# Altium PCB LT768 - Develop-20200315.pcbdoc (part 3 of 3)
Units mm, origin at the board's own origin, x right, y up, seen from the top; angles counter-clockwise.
Board outline 114.72 x 114.74 mm, 2 copper layers (Top Layer, Bottom Layer); 164 components, 138 nets, 704 pads, 858 vias.
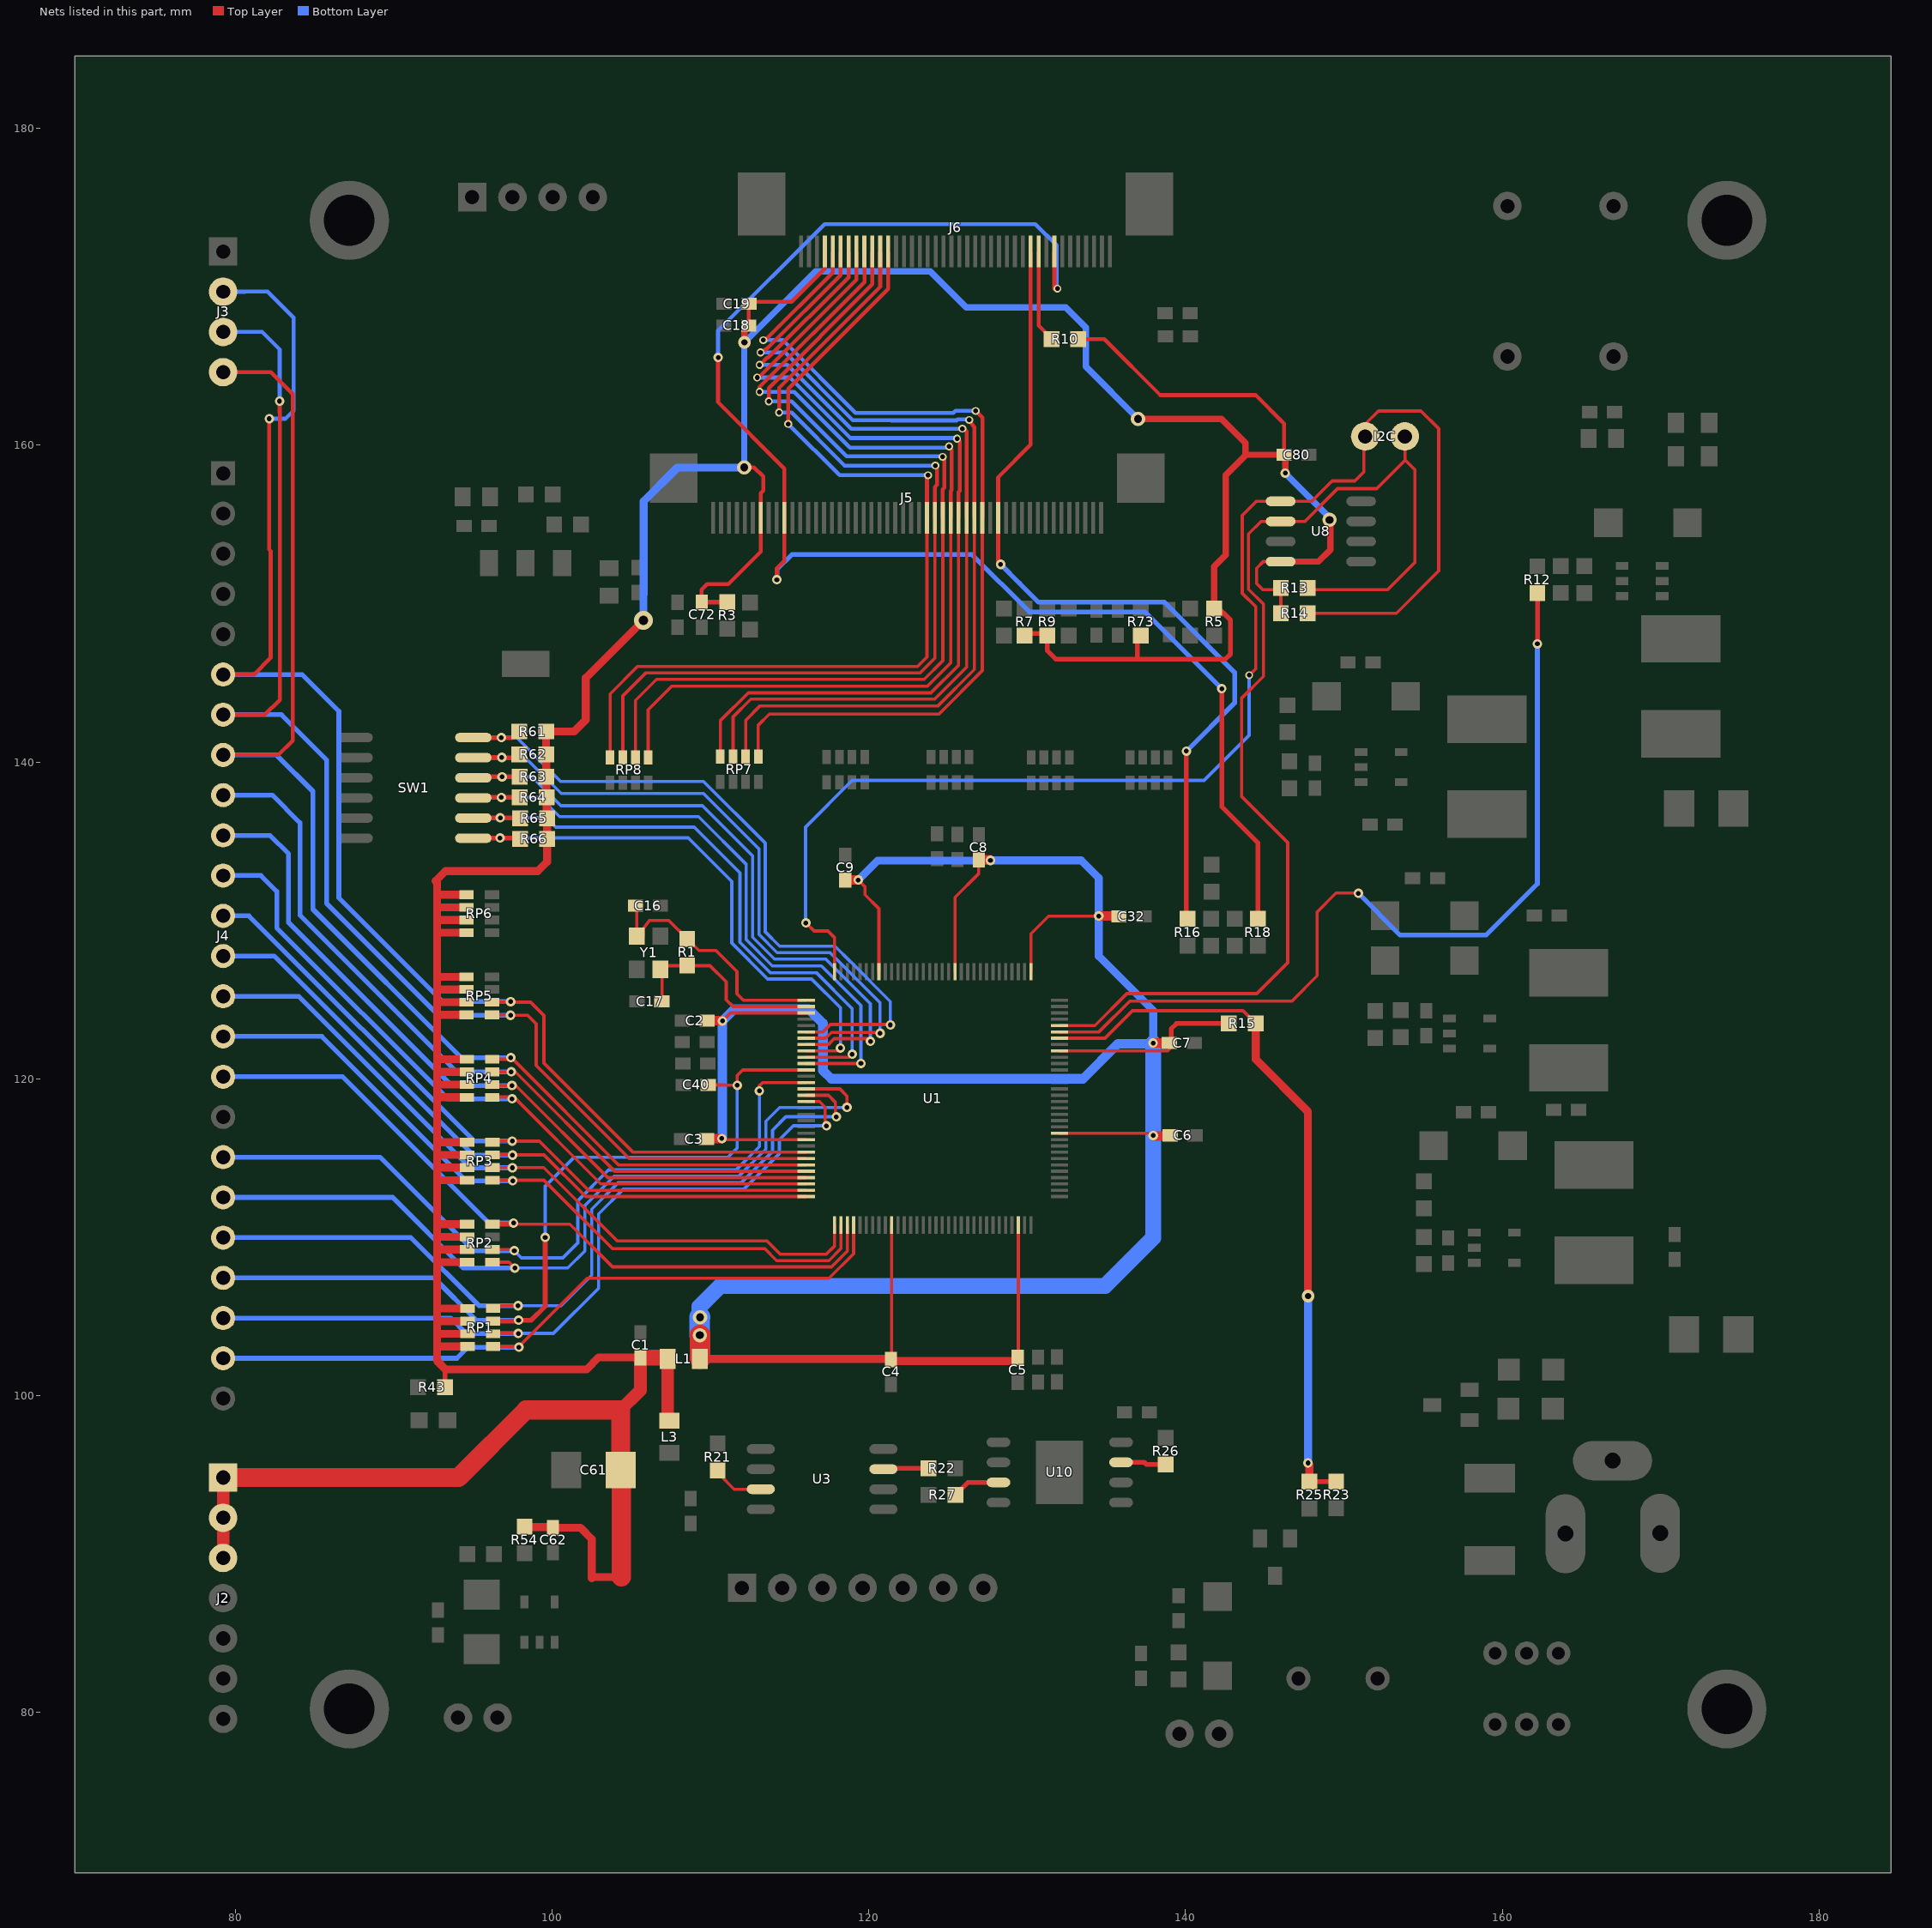
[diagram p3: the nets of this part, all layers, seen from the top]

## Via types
v1: diameter 0.6, hole 0.3, Top Layer to Bottom Layer, 743 vias
v2: diameter 0.5, hole 0.3, Top Layer to Bottom Layer, 82 vias
v3: diameter 0.9, hole 0.5, Top Layer to Bottom Layer, 20 vias
v4: diameter 1.2, hole 0.6, Top Layer to Bottom Layer, 7 vias
v5: diameter 0.8, hole 0.4, Top Layer to Bottom Layer, 6 vias

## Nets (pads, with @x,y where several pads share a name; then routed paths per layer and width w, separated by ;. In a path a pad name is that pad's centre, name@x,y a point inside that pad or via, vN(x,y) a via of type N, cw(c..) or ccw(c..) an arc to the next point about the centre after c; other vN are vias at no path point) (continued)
LT768_DB5_SDO: J3.2 J4.6 RP5.2 U1.25 | length 114.5
  Top Layer w0.2: RP5.2@96.55,124.84 v1@97.38,124.84 ; v1(97.38,124.87) v1@97.38,124.84 ; v1@97.38,124.84 98.64,124.84 ; v1@97.38,124.84 98.64,124.84 ; 98.64,124.84 99.48,124 ; 98.64,124.84 99.48,124 ; 99.48,120.994 105.114,115.36 ; 99.48,120.994 99.48,124 ; 99.48,120.994 105.114,115.36 ; 99.48,120.994 99.48,124 ; 105.114,115.36 U1.25@116.04,115.36 105.114,115.36
  Top Layer w0.25: J4.6@79.22,145.53 81.17,145.53 82.22,146.58 82.22,153.33 82.13,153.42 v1(82.13,161.68)
  Bottom Layer w0.25: J3.2@79.22,169.7 80.62,169.7 80.63,169.71 82.03,169.71 83.67,168.07 83.67,162.19 83.16,161.68 v1(82.13,161.68)
  Bottom Layer w0.3: J4.6@79.22,145.53 84.21,145.53 86.53,143.21 86.53,131.43 93.09,124.87 v1(97.38,124.87)
LT768_DB6_SDI: J3.3 J4.7 RP5.1 U1.26 | length 87.8
  Top Layer w0.2: U1.26@116.04,114.96 104.87,114.96 98.99,120.84 98.99,123.47 98.45,124.01 v1(97.37,124.01) ; v1(97.37,124.01) v1@97.37,124.04 ; v1(97.37,124.01) v1@97.37,124.04 ; v1@97.37,124.04 RP5.1@96.2,124.04 v1@97.37,124.04
  Top Layer w0.25: J4.7@79.22,142.99 81.86,142.99 82.795,143.925 82.795,162.045 82.79,162.05 v1(82.79,162.79)
  Bottom Layer w0.25: J3.3@79.22,167.16 81.68,167.16 82.79,166.05 v1(82.79,162.79)
  Bottom Layer w0.3: J4.7@79.22,142.99 82.9,142.99 85.75,140.14 85.75,131.08 92.82,124.01 v1(97.37,124.01)
  other v1: 97.37,124.01
LT768_DB7_SCLK: J3.4 J4.8 RP4.4 U1.27 | length 105.8
  Top Layer w0.2: RP4.4@96.56,121.23 v1@97.4,121.23 ; v1(97.39,121.34) 97.4,121.33 v1@97.4,121.23 ; v1@97.4,121.23 v1@97.526,121.23 ; v1@97.4,121.23 v1@97.526,121.23 ; v1@97.526,121.23 104.196,114.56 ; v1@97.526,121.23 104.196,114.56 ; 104.196,114.56 U1.27@116.04,114.56 104.196,114.56
  Top Layer w0.25: J4.8@79.22,140.45 82.71,140.45 83.61,141.35 83.61,163.24 82.23,164.62 J3.4@79.22,164.62
  Bottom Layer w0.3: J4.8@79.22,140.45 82.59,140.45 84.89,138.15 84.89,130.7 94.25,121.34 v1(97.39,121.34)
LT768_DB8: J4.9 RP4.3 U1.28 | length 72.2
  Top Layer w0.2: RP4.3@96.56,120.43 96.57,120.44 v1(97.41,120.44) ; v1(97.41,120.44) v1@97.426,120.456 ; v1(97.41,120.44) v1@97.426,120.456 ; v1@97.426,120.456 v1@97.65,120.456 ; v1@97.426,120.456 v1@97.65,120.456 ; v1@97.65,120.456 103.946,114.16 ; v1@97.65,120.456 103.946,114.16 ; 103.946,114.16 U1.28@116.04,114.16 103.946,114.16
  Bottom Layer w0.3: J4.9@79.22,137.91 82.33,137.91 84.07,136.17 84.07,130.33 93.96,120.44 v1(97.41,120.44)
  other v1: 97.41,120.44
LT768_DB9: J4.10 RP4.2 U1.29 | length 70.3
  Top Layer w0.2: RP4.2@96.56,119.63 96.56,119.57 v1(97.46,119.57) ; v1(97.46,119.57) v1@97.7,119.57 ; v1(97.46,119.57) v1@97.7,119.57 ; v1@97.7,119.57 103.51,113.76 ; v1@97.7,119.57 103.51,113.76 ; 103.51,113.76 U1.29@116.04,113.76 103.51,113.76
  Bottom Layer w0.3: J4.10@79.22,135.37 82.18,135.37 83.35,134.2 83.35,129.86 93.64,119.57 v1(97.46,119.57)
  other v1: 97.46,119.57
LT768_DB10: J4.11 RP4.1 U1.30 | length 68.2
  Top Layer w0.2: RP4.1@96.56,118.83 96.56,118.85 v1@97.47,118.85 ; v1(97.47,118.73) v1@97.47,118.85 ; v1@97.47,118.85 v1@97.58,118.85 ; v1@97.47,118.85 v1@97.58,118.85 ; v1@97.58,118.85 103.07,113.36 ; v1@97.58,118.85 103.07,113.36 ; 103.07,113.36 U1.30@116.04,113.36 103.07,113.36
  Bottom Layer w0.3: J4.11@79.22,132.83 81.61,132.83 82.61,131.83 82.61,129.53 93.41,118.73 v1(97.47,118.73)
LT768_DB11: J4.12 RP3.4 U1.31 | length 64.8
  Top Layer w0.2: RP3.4@96.58,115.995 96.645,116.06 v1(97.48,116.06) ; v1(97.48,116.06) 99.2,116.06 ; v1(97.48,116.06) 99.2,116.06 ; 99.2,116.06 102.3,112.96 ; 99.2,116.06 102.3,112.96 ; 102.3,112.96 U1.31@116.04,112.96 102.3,112.96
  Bottom Layer w0.3: J4.12@79.22,130.29 80.85,130.29 95.08,116.06 v1(97.48,116.06)
  other v1: 97.48,116.06
LT768_DB12: J4.13 RP3.3 U1.32 | length 67.9
  Top Layer w0.2: RP3.3@96.58,115.195 v1@97.47,115.195 ; U1.32@116.04,112.56 102.12,112.56 99.485,115.195 v1@97.489,115.195 ; v1@97.47,115.195 v1(97.5,115.18) ; v1@97.47,115.195 v1(97.5,115.18) ; v1@97.47,115.195 v1@97.485,115.195 ; v1@97.47,115.195 v1@97.47,115.24 ; v1@97.47,115.195 v1@97.47,115.24 ; v1@97.47,115.195 v1@97.485,115.195 ; v1@97.47,115.195 v1(97.5,115.18) ; v1@97.47,115.24 v1@97.489,115.195 ; v1@97.47,115.24 v1@97.489,115.195 ; v1@97.485,115.195 v1@97.489,115.195 ; v1@97.485,115.195 v1@97.489,115.195 ; v1@97.485,115.195 v1(97.5,115.18) ; v1@97.485,115.195 v1(97.5,115.18) ; v1@97.489,115.195 97.5,115.184 v1(97.5,115.18)
  Bottom Layer w0.3: 82.43,127.75 95,115.18 ; 82.43,127.75 J4.13@79.22,127.75 82.43,127.75 ; 82.43,127.75 95,115.18 ; 95,115.18 v1(97.5,115.18) 95,115.18
  other v1: 97.5,115.18
LT768_DB13: J4.14 RP3.2 U1.33 | length 72
  Top Layer w0.2: RP3.2@96.58,114.395 v1@97.505,114.395 ; v1(97.49,114.38) v1@97.505,114.395 ; v1@97.505,114.395 99.471,114.395 ; v1@97.505,114.395 99.471,114.395 ; 99.471,114.395 104.106,109.76 ; 99.471,114.395 104.106,109.76 ; 104.106,109.76 113.57,109.76 ; 104.106,109.76 113.57,109.76 ; 113.57,109.76 114.41,108.92 ; 113.57,109.76 114.41,108.92 ; 114.41,108.92 117.31,108.92 ; 114.41,108.92 117.31,108.92 ; 117.31,108.92 117.84,109.45 ; 117.31,108.92 117.84,109.45 ; 117.84,109.45 U1.33@117.84,110.76 117.84,109.45
  Bottom Layer w0.3: J4.14@79.22,125.21 83.99,125.21 94.82,114.38 v1(97.49,114.38)
LT768_DB14: J4.15 RP3.1 U1.34 | length 72.3
  Top Layer w0.2: RP3.1@96.58,113.595 v1@97.54,113.595 ; v1(97.51,113.56) 97.51,113.565 v1@97.54,113.595 ; v1@97.54,113.595 99.485,113.595 ; v1@97.54,113.595 99.485,113.595 ; 99.485,113.595 103.81,109.27 ; 99.485,113.595 103.81,109.27 ; 103.81,109.27 113.432,109.27 ; 103.81,109.27 113.432,109.27 ; 113.432,109.27 114.182,108.52 ; 113.432,109.27 114.182,108.52 ; 114.182,108.52 117.476,108.52 ; 114.182,108.52 117.476,108.52 ; 117.476,108.52 118.24,109.284 ; 117.476,108.52 118.24,109.284 ; 118.24,109.284 U1.34@118.24,110.76 118.24,109.284
  Bottom Layer w0.3: J4.15@79.22,122.67 85.45,122.67 94.56,113.56 v1(97.51,113.56)
LT768_DB15: J4.16 RP2.4 U1.35 | length 49.2
  Top Layer w0.2: v1@97.56,110.815 101.115,110.815 103.81,108.12 117.641,108.12 118.64,109.119 U1.35@118.64,110.76
  Top Layer w0.3: v1(97.56,110.89) v1@97.56,110.815 ; v1@97.56,110.815 RP2.4@96.231,110.815 v1@97.56,110.815
  Bottom Layer w0.3: J4.16@79.22,120.13 86.77,120.13 96.01,110.89 v1(97.56,110.89)
LT768_I2C_M_SCL: I2C.1 R13.2 U1.92 U8.6 | length 74.4
  Top Layer w0.2: U1.92@132.04,123.36 134.272,123.36 136.292,125.38 144.499,125.38 146.45,127.331 146.45,134.91 143.55,137.81 143.55,144.04 144.92,145.41 144.92,149.97 143.98,150.91 143.98,154.405 144.77,155.195 U8.6@146.01,155.195 147.535,155.195 149.6,157.26 152.07,157.26 153.86,159.05 ; R13.2@147.72,150.99 147.82,150.89 152.77,150.89 154.48,152.6 154.48,158.46 153.89,159.05 153.86,159.05 ; 153.86,159.05 I2C.1@153.86,160.55 ; 153.86,159.05 I2C.1@153.86,160.55 ; I2C.1@153.86,160.55 I2C.1@153.85,160.56 I2C.1@153.86,160.55
LT768_I2C_M_SDA: I2C.2 R14.2 U1.128 U8.5 | length 90.9
  Top Layer w0.2: v1(116.03,129.84) 116.54,129.33 117.41,129.33 117.84,128.9 U1.128@117.84,126.76 ; v2(144.02,145.48) 144.43,145.89 144.43,149.81 143.58,150.66 143.58,155.57 144.475,156.465 U8.5@146.01,156.465 147.975,156.465 149.26,157.75 150.69,157.75 151.26,158.32 151.26,160.47 I2C.2@151.35,160.56 151.35,161.34 152.18,162.17 154.87,162.17 155.99,161.05 155.99,152.07 153.32,149.4 R14.2@147.72,149.4
  Bottom Layer w0.2: v1(116.03,129.84) 116,129.84 116,135.89 118.95,138.84 141.17,138.84 144.02,141.69 v2(144.02,145.48)
LT768_INT: J4.23 RP1.1 U1.36 | length 47.7
  Top Layer w0.2: v1(97.9,103.05) v1@97.9,103.08 ; U1.36@119.04,110.76 119.04,108.953 117.487,107.4 102.22,107.4 v1@97.9,103.08 ; RP1.1@96.26,103.08 v1@97.9,103.08 ; RP1.1@96.26,103.08 RP1.1@96.26,103.096 RP1.1@96.26,103.08 ; RP1.1@96.26,103.08 v1@97.9,103.08
  Bottom Layer w0.3: J4.23@79.22,102.35 93.99,102.35 94.69,103.05 v1(97.9,103.05)
LT768_PS0: R64.1 SW1.9 U1.11 | length 42.2
  Top Layer w0.2: U1.11@116.04,120.96 v1@119.5,120.96 ; v1@119.48,120.96 v1@119.5,120.94 ; v1@119.48,120.96 v1(119.5,120.97) ; v1@119.48,120.96 v1(119.5,120.97) ; v1@119.48,120.96 v1@119.5,120.94 ; v1@119.5,120.94 v1@119.5,120.96 ; v1@119.5,120.94 v1@119.5,120.96 ; v1@119.5,120.96 v1(119.5,120.97)
  Top Layer w0.3: SW1.9@95.13,137.735 95.155,137.76 v1(96.79,137.76) ; v1(96.79,137.76) R64.1@97.95,137.76 v1(96.79,137.76)
  Bottom Layer w0.2: v1(96.79,137.76) 99.26,137.76 100.467,136.553 109.24,136.553 112.26,133.533 112.26,128.78 113.91,127.13 117,127.13 119.5,124.63 v1(119.5,120.97)
  other v1: 119.5,120.97 96.79,137.76
LT768_PS1: R65.1 SW1.8 U1.10 | length 40.4
  Top Layer w0.2: U1.10@116.04,121.36 118.76,121.36 v1(118.95,121.55) ; R65.1@98.025,136.48 R65.1@98.1,136.39 ; R65.1@98.025,136.48 98,136.48 R65.1@98.025,136.48 ; R65.1@98.025,136.48 R65.1@98.1,136.39 ; R65.1@98.04,136.45 R65.1@97.98,136.45 R65.1@98.04,136.45 ; R65.1@98.04,136.45 R65.1@98.1,136.39 ; R65.1@98.04,136.45 R65.1@98.1,136.39
  Top Layer w0.3: SW1.8@95.13,136.465 95.13,136.48 v1(96.72,136.48) ; v1(96.72,136.48) 98,136.48 v1(96.72,136.48)
  Bottom Layer w0.2: v1(96.72,136.48) 99.64,136.48 100.23,135.89 108.97,135.89 111.86,133 111.86,128.615 113.775,126.7 116.68,126.7 118.95,124.43 v1(118.95,121.55)
  other v1: 96.72,136.48
LT768_PS2: R66.1 SW1.7 U1.9 | length 37.2
  Top Layer w0.2: v1(96.71,135.21) 97.98,135.21 R66.1@97.98,135.14 ; U1.9@116.04,121.76 118.03,121.76 v1(118.21,121.94)
  Top Layer w0.3: SW1.7@95.13,135.195 97.925,135.195 R66.1@97.98,135.14
  Bottom Layer w0.2: v1(96.71,135.21) 108.59,135.21 111.34,132.46 111.34,128.569 113.609,126.3 116.39,126.3 118.21,124.48 v1(118.21,121.94)
LT768_PWM0: R15.2 R23.1 R25.1 U1.90 | length 45.8
  Top Layer w0.2: U1.90@132.04,122.56 134.92,122.56 136.65,124.29 143.63,124.29 R15.2@144.43,123.49 ; v5@147.73,106.28 v5(147.74,106.28) ; R23.1@149.516,94.574 149.658,94.574 R23.1@149.67,94.563
  Top Layer w0.3: v1(147.73,95.74) v1@147.828,95.642 ; R25.1@147.828,94.563 R23.1@149.67,94.563
  Top Layer w0.5: R15.2@144.43,123.49 144.43,121.23 147.73,117.93 v5@147.73,106.28 ; R25.1@147.828,94.563 v1@147.828,95.642
  Bottom Layer w0.5: v1(147.73,95.74) 147.74,95.74 v5(147.74,106.28)
LT768_PWM1: R12.1 U1.91 | length 57
  Top Layer w0.2: U1.91@132.04,122.96 134.53,122.96 136.48,124.91 146.72,124.91 148.31,126.5 148.31,130.53 149.505,131.725 150.905,131.725 v1(150.92,131.71) ; R12.1@162.22,150.66 R12.1@162.24,150.63
  Top Layer w0.3: v1(162.22,147.46) 162.24,147.48 R12.1@162.24,150.63
  Bottom Layer w0.3: v1(150.92,131.71) 153.56,129.07 158.98,129.07 162.22,132.31 v1(162.22,147.46)
LT768_RD#: J4.18 RP2.2 U1.14 | length 69.8
  Top Layer w0.2: RP2.2@96.581,109.215 97.535,109.215 v1(97.61,109.14) ; v1(113.09,119.23) 113.09,119.54 113.08,119.55 113.29,119.76 U1.14@116.04,119.76
  Bottom Layer w0.2: v1(97.61,109.14) 98.06,108.69 100.669,108.69 101.62,109.641 101.62,112.3 103.56,114.24 111.61,114.24 113.09,115.72 v1(113.09,119.23)
  Bottom Layer w0.3: 89.12,115.05 J4.18@79.22,115.05 89.12,115.05 ; 89.12,115.05 95.03,109.14 ; 89.12,115.05 95.03,109.14 ; 95.03,109.14 v1(97.61,109.14) 95.03,109.14
  other v1: 97.61,109.14
LT768_RS/A0: J4.20 RP1.4 U1.16 | length 73.4
  Top Layer w0.2: RP1.4@96.61,105.496 96.784,105.67 v1(97.85,105.67) ; U1.16@116.04,118.96 117.45,118.96 117.88,118.53 117.88,117.69 117.95,117.62 v1(117.95,117.6)
  Bottom Layer w0.2: v1(97.85,105.67) 100.58,105.67 102.5,107.59 102.5,111.77 104.16,113.43 111.936,113.43 113.92,115.414 113.92,116.756 114.764,117.6 v1(117.95,117.6)
  Bottom Layer w0.3: 91.08,109.97 J4.20@79.22,109.97 91.08,109.97 ; 91.08,109.97 95.38,105.67 ; 91.08,109.97 95.38,105.67 ; 95.38,105.67 v1(97.85,105.67) 95.38,105.67
  other v1: 97.85,105.67
LT768_RST: C40.1 J4.21 RP1.3 U1.12 | length 58.6
  Top Layer w0.2: U1.12@116.04,120.56 112.04,120.56 111.69,120.21 v1(111.69,119.59) ; 110.889,119.611 C40.1@109.861,119.611 110.889,119.611 ; 110.889,119.611 110.91,119.59 ; 110.889,119.611 110.91,119.59 ; 110.91,119.59 v1(111.69,119.59) ; 110.91,119.59 v1(111.69,119.59)
  Top Layer w0.3: v1(99.56,109.98) 99.56,105.64 98.68,104.76 v1(97.88,104.76) ; v1@97.88,104.696 v1(97.88,104.76) ; v1@97.88,104.696 RP1.3@96.26,104.696 v1@97.88,104.696 ; v1@97.88,104.696 v1(97.88,104.76)
  Bottom Layer w0.2: v1(99.56,109.98) 99.56,113.21 101.4,115.05 111.11,115.05 111.69,115.63 v1(111.69,119.59)
  Bottom Layer w0.3: J4.21@79.22,107.43 92.53,107.43 95.2,104.76 v1(97.88,104.76)
  other v1: 97.88,104.76 111.69,119.59
LT768_TEST[0]: R63.1 SW1.10 U1.8 | length 43.5
  Top Layer w0.2: SW1.10@95.185,139.06 95.195,139.07 SW1.10@95.53,139.07 ; U1.8@116.04,122.16 117.44,122.16 117.81,122.53 119.99,122.53 120.11,122.41 v1(120.1,122.36)
  Top Layer w0.3: SW1.10@95.53,139.07 R63.1@97.94,139.07 ; v1(96.84,139.06) SW1.10@95.185,139.06 ; SW1.10@95.185,139.06 95.13,139.005 SW1.10@95.185,139.06
  Bottom Layer w0.2: v1(96.84,139.06) 98.73,139.06 100.55,137.24 109.49,137.24 112.66,134.07 112.66,128.946 114.046,127.56 114.737,127.56 114.74,127.563 117.28,127.563 120.1,124.743 v1(120.1,122.36)
LT768_TEST[1]: R62.1 SW1.11 U1.7 | length 44.8
  Top Layer w0.2: U1.7@116.04,122.56 117.27,122.56 117.64,122.93 120.438,122.93 v1(120.71,122.87)
  Top Layer w0.3: v1(96.82,140.29) 95.145,140.29 95.13,140.275 97.735,140.275 R62.1@97.93,140.47
  Bottom Layer w0.2: v1(96.82,140.29) 98.29,140.29 100.57,138.01 109.56,138.01 113.06,134.51 113.06,129.114 114.204,127.97 117.55,127.97 120.71,124.81 v1(120.71,122.87)
LT768_TEST[2]: R61.1 SW1.12 U1.6 | length 47.8
  Top Layer w0.2: U1.6@116.04,122.96 117.1,122.96 117.57,123.43 121.36,123.43 v1(121.36,123.4)
  Top Layer w0.3: SW1.12@95.13,141.545 R61.1@97.49,141.545 ; v1(96.79,141.54) 95.98,141.545 R61.1@97.49,141.545 ; R61.1@97.49,141.545 R61.1@97.775,141.83 ; R61.1@97.49,141.545 R61.1@97.775,141.83 ; R61.1@97.775,141.83 R61.1@97.92,141.83 ; R61.1@97.775,141.83 R61.1@97.92,141.83 ; R61.1@97.92,141.83 R61.1@97.92,141.93 R61.1@97.92,141.83
  Bottom Layer w0.2: v1(96.79,141.54) 97.77,141.54 100.53,138.78 109.56,138.78 113.46,134.88 113.46,129.28 114.37,128.37 117.856,128.37 118.822,127.404 118.833,127.404 121.36,124.877 v1(121.36,123.4)
LT768_VDD3.3V: C2.1 C3.1 C4.1 C5.1 C6.1 C7.1 C8.1 C9.1 C32.1 L1.2 R15.1 U1.3 U1.23 U1.42 U1.62 U1.75 U1.88 U1.97 U1.109 U1.121 | length 270.4
  Top Layer w0.2: C3.1@109.747,116.19 C3.1@109.787,116.23 ; v1@110.605,123.666 110.61,123.662 v1(110.75,123.65) ; C4.1@121.4,102.277 121.4,102.53 121.44,102.57 U1.42@121.44,110.76 ; U1.109@125.44,126.76 125.44,131.46 126.944,132.964 C8.1@126.944,133.825 ; C5.1@129.258,102.18 C5.1@129.4,102.397 129.44,102.397 U1.62@129.44,110.76 ; U1.88@132.04,121.76 138.87,121.76 139.01,121.9 139.01,122.23 C7.1@138.984,122.256 ; C32.1@135.769,130.27 C32.1@135.796,130.243 ; v1@137.97,116.39 137.97,116.41 v1(137.96,116.42) ; v1@110.75,116.23 v1@110.82,116.16 ; v1@110.75,116.23 v1(110.72,116.23) v1@110.75,116.23 ; v1@110.75,116.23 v1@110.82,116.16 ; v1(110.75,123.65) 111.26,124.16 ; v1(110.75,123.65) 111.26,124.16 ; v1(110.75,123.65) 111.26,124.16 ; v1@110.82,116.16 U1.23@116.04,116.16 v1@110.82,116.16 ; 111.26,124.16 U1.3@116.04,124.16 ; 111.26,124.16 U1.3@116.04,124.16 ; 111.26,124.16 U1.3@116.04,124.16 ; 119.754,131.626 119.754,132.126 ; 119.754,131.626 120.64,130.74 ; 119.754,131.626 119.754,132.126 ; 119.754,131.626 120.64,130.74 ; 119.754,132.126 v1(119.33,132.55) 119.754,132.126 ; 120.64,130.74 U1.121@120.64,126.76 120.64,130.74 ; U1.97@130.24,126.76 130.24,129.16 ; U1.97@130.24,126.76 130.24,129.16 ; U1.97@130.24,126.76 130.24,129.16 ; 130.24,129.16 131.35,130.27 ; 130.24,129.16 131.35,130.27 ; 130.24,129.16 131.35,130.27 ; 131.35,130.27 v1(134.52,130.27) ; 131.35,130.27 v1(134.52,130.27) ; 131.35,130.27 v1(134.52,130.27) ; U1.75@132.04,116.56 v1@137.82,116.56 ; U1.75@132.04,116.56 v1@137.82,116.56 ; U1.75@132.04,116.56 v1@137.82,116.56 ; U1.75@132.04,116.56 v1@137.82,116.56 ; v1@137.82,116.56 v1(137.96,116.42) ; v1@137.82,116.56 v1(137.96,116.42) ; v1@137.82,116.56 v1(137.96,116.42) ; v1@137.82,116.56 v1(137.96,116.42) ; C7.1@138.984,122.256 138.98,122.26 C7.1@138.984,122.256 ; v3@109.33,104.93 v3(109.34,104.94) v3@109.33,104.93 ; v1@127.645,133.825 v1(127.68,133.79) v1@127.645,133.825
  Top Layer w0.3: C7.1@138.984,122.256 138.984,122.314 139.09,122.42 139.09,123.15 139.43,123.49 R15.1@142.73,123.49
  Top Layer w0.5: L1.2@109.327,102.312 121.4,102.312 C4.1@121.4,102.277 121.52,102.18 C5.1@129.258,102.18 ; C9.1@118.509,132.543 C9.1@118.516,132.55
  Top Layer w0.6: C3.1@109.787,116.23 v1(110.72,116.23) ; C2.1@109.787,123.666 v1@110.605,123.666 ; C9.1@118.516,132.55 v1(119.33,132.55) ; v1(134.52,130.27) C32.1@135.769,130.27 ; v1@137.97,116.39 139.032,116.39 C6.1@139.032,116.426 ; C8.1@126.944,133.825 127.645,133.825 C8.1@126.944,133.825 ; v1(137.95,122.26) 138.98,122.26 v1(137.95,122.26)
  Top Layer w1: L1.2@109.327,102.312 L1.2@109.33,102.315
  Top Layer w1.3: L1.2@109.33,102.315 v3(109.33,103.81)
  Bottom Layer w0.2: v1(110.72,116.23) v1@110.75,116.26
  Bottom Layer w0.5: v1(119.33,132.55) 120.55,133.77 127.66,133.77 v1(127.68,133.79) 133.41,133.79 134.52,132.68 v1(134.52,130.27) 134.52,127.74 137.96,124.3 137.96,122.25 v1(137.95,122.26)
  Bottom Layer w0.6: v1@110.75,116.26 v1(110.75,123.65) 111.5,124.4 116.2,124.4 117.1,123.5 117.1,120.52 117.62,120 133.52,120 135.73,122.21 137.9,122.21 v1(137.95,122.26)
  Bottom Layer w1: v3@109.31,104.94 109.31,105.62 110.61,106.92 134.92,106.92 137.96,109.96 v1(137.96,116.42) ; v1(137.96,116.42) 137.96,122.25 v1(137.96,116.42)
  Bottom Layer w1.3: v3(109.33,103.81) 109.3,103.81 109.3,104.94 v3@109.31,104.94 ; v3@109.31,104.94 v3(109.34,104.94) v3@109.31,104.94
  other v1: 110.72,116.23 137.96,116.42 137.96,116.42 137.95,122.26 110.75,123.65 110.75,123.65 134.52,130.27 134.52,130.27 119.33,132.55 127.68,133.79
  other v3: 109.34,104.94
LT768_WAIT: J4.22 RP1.2 U1.17 | length 70.1
  Top Layer w0.2: RP1.2@96.61,103.896 96.634,103.92 v1(97.86,103.92) ; U1.17@116.04,118.56 116.89,118.56 117.24,118.21 117.24,117.17 117.33,117.08 v1(117.33,117.03)
  Bottom Layer w0.2: v1(97.86,103.92) 100.08,103.92 102.93,106.77 102.93,111.47 104.49,113.03 112.101,113.03 114.35,115.279 114.35,116.15 115.23,117.03 v1(117.33,117.03)
  Bottom Layer w0.3: 93.6,104.89 J4.22@79.22,104.89 93.6,104.89 ; 93.6,104.89 94.58,103.91 ; 93.6,104.89 94.58,103.91 ; 94.58,103.91 96.14,103.91 ; 94.58,103.91 96.14,103.91 ; 96.14,103.91 96.15,103.92 ; 96.14,103.91 96.15,103.92 ; 96.15,103.92 v1(97.86,103.92) 96.15,103.92
  other v1: 97.86,103.92
LT768_WR#: J4.19 RP2.1 U1.15 | length 73.1
  Top Layer w0.2: RP2.1@96.581,108.415 97.275,108.415 v1(97.64,108.05) ; U1.15@116.04,119.36 118.17,119.36 118.62,118.91 v1(118.62,118.19)
  Bottom Layer w0.2: v1(97.64,108.05) 100.98,108.05 102.06,109.13 102.06,111.99 103.91,113.84 111.78,113.84 113.5,115.56 113.5,117.32 114.37,118.19 v1(118.62,118.19)
  Bottom Layer w0.3: 89.93,112.51 J4.19@79.22,112.51 89.93,112.51 ; 89.93,112.51 94.39,108.05 ; 89.93,112.51 94.39,108.05 ; 94.39,108.05 v1(97.64,108.05) 94.39,108.05
  other v1: 97.64,108.05
LT768_XI: C16.1 R1.2 U1.1 Y1.3 | length 16.3
  Top Layer w0.2: C16.1@105.263,130.93 105.34,130.853 Y1.3@105.34,129.01 105.74,129.01 105.74,129.46 106.14,129.99 107.377,129.99 R1.2@108.527,128.84 109.267,128.1 110.34,128.1 111.67,126.77 111.67,125.37 112.08,124.96 U1.1@116.04,124.96
LT768_XO: C17.2 R1.1 U1.2 Y1.1 | length 13.3
  Top Layer w0.2: C17.2@106.937,124.89 106.937,126.91 Y1.1@106.84,126.91 106.84,127.14 R1.1@108.527,127.14 109.97,127.14 110.99,126.12 110.99,124.99 111.42,124.56 U1.2@116.04,124.56
M_FLASH_HOLD: R26.2 U10.7 | length 2.9
  Top Layer w0.3: U10.7@135.93,95.78 137.392,95.78 137.536,95.636 R26.2@138.748,95.636
M_FLASH_HOLD#: R21.2 U3.7 | length 3.3
  Top Layer w0.2: R21.2@110.45,95.27 110.58,95.14 110.58,95 111.5,94.08 U3.7@113.18,94.08
M_FLASH_WP: R27.1 U10.3 | length 3
  Top Layer w0.3: R27.1@125.471,93.711 126.27,94.51 U10.3@128.19,94.51
M_FLASH_WP#: R22.1 U3.3 | length 2.9
  Top Layer w0.2: U3.3@120.92,95.35 U3.3@120.97,95.4
  Top Layer w0.3: U3.3@120.97,95.4 R22.1@123.76,95.4
ON/OFF: J6.31 R10.1 | length 5.9
  Top Layer w0.25: J6.31@130.72,172.24 130.72,167.56 131.53,166.75 R10.1@131.53,166.71
PCLK: J5.37 J6.30 R16.1 | length 55.1
  Top Layer w0.25: v1(128.32,152.48) 128.17,152.63 J5.37@128.17,155.43 128.17,157.99 130.22,160.04 J6.30@130.22,172.24
  Top Layer w0.3: v1(140.05,140.69) 140.05,130.24 R16.1@140.13,130.1
  Bottom Layer w0.3: v1(128.32,152.48) 129.525,151.285 130.72,150.09 138.67,150.09 143.11,145.65 143.11,143.74 140.06,140.69 v1(140.05,140.69)
R0: J5.35 J6.5 RP7.5 | length 57.1
  Top Layer w0.2: RP7.5@113.019,140.346 113.019,142.339 113.71,143.03 124.426,143.03 127.17,145.774 J5.35@127.17,155.43
  Top Layer w0.25: v2(113.33,166.64) 113.39,166.58 117.72,170.911 J6.5@117.72,172.24 ; v2(126.75,162.17) 127.17,161.75 J5.35@127.17,155.43
  Bottom Layer w0.25: v2(113.33,166.64) 114.57,166.64 119.17,162.04 125.336,162.04 125.476,162.18 126.75,162.18 v2(126.75,162.17)
R1: J5.34 J6.6 RP7.6 | length 57.5
  Top Layer w0.2: RP7.6@112.219,140.346 112.219,142.64 113.129,143.55 124.38,143.55 126.67,145.84 J5.34@126.67,155.43
  Top Layer w0.25: v2(113.16,165.86) 113.17,165.846 113.649,166.18 118.22,170.751 J6.6@118.22,172.24 ; v2(126.34,161.6) 126.67,161.117 J5.34@126.67,155.43
  Bottom Layer w0.25: v2(113.16,165.86) 114.714,165.86 118.984,161.59 121.389,161.59 121.409,161.57 125.555,161.57 125.615,161.63 126.31,161.63 v2(126.34,161.6)
R2: J5.33 J6.7 RP7.7 | length 57.9
  Top Layer w0.2: RP7.7@111.419,140.346 111.419,140.579 111.43,140.59 111.43,142.85 112.55,143.97 124.16,143.97 126.17,145.98 J5.33@126.17,155.43
  Top Layer w0.25: v2(113.1,165.08) 113.113,165.067 113.577,165.53 113.635,165.53 118.72,170.615 J6.7@118.72,172.24 ; v2(125.9,161.05) 125.96,161.11 126.185,160.885 126.185,157 126.17,156.985 J5.33@126.17,155.43
  Bottom Layer w0.25: v2(113.1,165.08) 114.857,165.08 118.887,161.05 v2(125.9,161.05)
R3: J5.32 J6.8 RP7.8 | length 58.1
  Top Layer w0.2: RP7.8@110.619,140.346 110.619,142.605 112.384,144.37 123.92,144.37 125.67,146.12 J5.32@125.67,155.43
  Top Layer w0.25: v2(112.95,164.28) 112.997,164.233 119.22,170.457 J6.8@119.22,172.24 ; v2(125.57,160.42) 125.735,160.255 125.735,157.11 125.67,157.045 J5.32@125.67,155.43
  Bottom Layer w0.25: v2(112.95,164.28) 115.021,164.28 118.841,160.46 125.57,160.46 v2(125.57,160.42)
R4: J5.31 J6.9 RP8.5 | length 62.2
  Top Layer w0.2: RP8.5@106.06,140.3 106.06,143.3 107.54,144.78 123.69,144.78 125.17,146.26 J5.31@125.17,155.43
  Top Layer w0.25: v2(113.1,163.37) 113.1,163.683 119.72,170.303 J6.9@119.72,172.24 ; v2(125.07,159.93) 125.235,159.744 125.235,157.17 125.17,157.105 J5.31@125.17,155.43
  Bottom Layer w0.25: v2(113.1,163.37) 115.294,163.37 118.814,159.85 125.043,159.85 125.043,159.903 v2(125.07,159.93)
R5: J5.30 J6.10 RP8.6 | length 61.6
  Top Layer w0.2: RP8.6@105.26,140.3 105.26,143.89 106.59,145.22 123.49,145.22 124.67,146.4 J5.30@124.67,155.43
  Top Layer w0.25: v2(113.68,162.78) 113.68,163.623 120.22,170.163 J6.10@120.22,172.24 ; v2(124.66,159.27) 124.775,159.155 124.775,157.33 124.67,157.225 J5.30@124.67,155.43
  Bottom Layer w0.25: v2(113.68,162.78) 115.12,162.78 118.6,159.3 124.66,159.3 v2(124.66,159.27)
R6: J5.29 J6.11 RP8.7 | length 60.9
  Top Layer w0.2: RP8.7@104.46,140.3 104.46,144.18 105.9,145.62 123.23,145.62 124.17,146.56 J5.29@124.17,155.43
  Top Layer w0.25: v2(114.33,162.07) 114.33,163.628 120.72,170.018 J6.11@120.72,172.24 ; J5.29@124.17,155.43 124.17,157.365 124.315,157.51 124.315,158.605 v2(124.2,158.72)
  Bottom Layer w0.25: v2(114.33,162.07) 115.12,162.07 118.47,158.72 v2(124.2,158.72)
R7: J5.28 J6.12 RP8.8 | length 60.2
  Top Layer w0.2: RP8.8@103.66,140.3 103.66,144.3 105.39,146.03 123.07,146.03 123.67,146.63 J5.28@123.67,155.43
  Top Layer w0.25: v2(114.91,161.35) 114.91,163.567 121.22,169.877 J6.12@121.22,172.24 ; J5.28@123.67,155.43 123.67,158.04 v2(123.74,158.11)
  Bottom Layer w0.25: v2(114.91,161.35) 118.15,158.11 v2(123.74,158.11)
VDD_3.3V: C1.1 C18.1 C19.1 C61.1 C62.1 C72.1 C80.1 J2.1 J2.2 J2.3 J5.7 J6.4 L1.1 L3.1 R3.1 R5.1 R7.1 R9.1 R10.2 R13.1 R14.1 R43.1 R54.2 R61.2 R62.2 R63.2 R64.2 R65.2 R66.2 R73.2 RP1.5 RP1.6 RP1.7 RP1.8 RP2.5 RP2.6 RP2.7 RP2.8 RP3.5 RP3.6 RP3.7 RP3.8 RP4.5 RP4.6 RP4.7 RP4.8 RP5.5 RP5.6 RP5.7 RP5.8 RP6.5 RP6.6 RP6.7 RP6.8 U8.8 | length 490.5
  Top Layer w0.2: L3.1@107.295,98.68 107.41,98.565 L3.1@107.41,98.406 ; U8.8@146.01,152.655 144.91,152.655 144.49,152.235 144.49,151.28 ; R14.1@146.02,149.4 R13.1@146.02,150.89 ; 144.49,151.28 144.88,150.89 ; 144.49,151.28 144.88,150.89 ; 144.49,151.28 144.88,150.89 ; 144.88,150.89 R13.1@146.02,150.89 ; 144.88,150.89 R13.1@146.02,150.89 ; 144.88,150.89 R13.1@146.02,150.89 ; R13.1@146.02,150.89 R13.1@146.02,150.99 R13.1@146.02,150.89
  Top Layer w0.25: C72.1@109.45,150.092 109.44,150.102 109.44,150.83 109.44,150.89 109.79,151.24 111.13,151.24 113.17,153.28 J5.7@113.17,155.43 ; J6.4@117.22,172.24 117.22,171.153 115.127,169.06 C19.1@112.417,169.06 ; R10.2@133.23,166.71 134.87,166.71 138.41,163.17 144.43,163.17 146.225,161.375 C80.1@146.225,159.402 C80.1@146.225,159.57 ; C18.1@112.24,167.56 C18.1@112.417,167.56 ; C18.1@112.24,167.56 112.14,167.46 C18.1@112.24,167.56 ; C18.1@112.24,167.56 C18.1@112.417,167.56 ; C19.1@112.32,169.06 C19.1@112.437,168.943 ; C19.1@112.32,169.06 C19.1@112.417,169.06 ; C19.1@112.32,169.06 C19.1@112.437,168.943 ; C19.1@112.32,169.06 C19.1@112.417,169.06 ; C18.1@112.417,167.56 C19.1@112.417,169.06 ; C19.1@112.437,168.943 C19.1@112.437,168.93 C19.1@112.437,168.943 ; 112.75,158.61 113.33,158.03 ; 112.75,158.61 v3(112.13,158.61) 112.75,158.61 ; 112.75,158.61 113.33,158.03 ; J5.7@113.17,155.43 113.17,156.98 ; J5.7@113.17,155.43 113.17,156.98 ; 113.17,156.98 113.33,157.14 ; 113.17,156.98 113.33,157.14 ; 113.33,157.14 113.33,158.03 ; 113.33,157.14 113.33,158.03
  Top Layer w0.3: C72.1@109.468,150.11 R3.1@111.07,150.11 ; R7.1@129.84,147.99 129.84,148.118 131.277,148.118 131.277,147.03 131.807,146.5 136.95,146.5 ; R5.1@141.81,149.69 141.81,149.92 141.88,149.92 142.84,148.96 142.84,146.82 142.52,146.5 136.95,146.5 ; 93.237,101.597 R43.1@93.237,100.526 93.237,101.597 ; 93.237,101.597 93.28,101.64 93.237,101.597 ; 136.95,146.5 R73.2@136.95,148.071 ; 136.95,146.5 R73.2@136.95,148.071 ; R73.2@136.95,148.071 R73.2@137.066,148.187 ; R73.2@136.95,148.071 R73.2@137.066,148.187 ; R73.2@137.066,148.187 R73.2@137.17,147.99 R73.2@137.066,148.187
  Top Layer w0.4: R5.1@141.81,149.69 141.81,152.355 142.54,153.085 142.54,158.12 143.792,159.372 ; U8.8@146.01,152.655 148.39,152.655 149.14,153.405 149.14,155.24 v3(149.09,155.29) ; C80.1@146.225,159.402 143.762,159.402 143.792,159.372 ; C80.1@146.225,159.57 146.3,159.495 v1(146.3,158.24) ; 142.265,161.67 143.792,160.143 ; 142.265,161.67 v3(137,161.67) 142.265,161.67 ; 142.265,161.67 143.792,160.143 ; 143.792,159.372 143.792,160.143 ; 143.792,159.372 143.792,160.143 ; v5(112.14,166.5) 112.14,167.46 v5(112.14,166.5)
  Top Layer w0.5: R54.2@98.26,91.73 98.26,91.686 100.06,91.686 C62.1@100.06,91.657 101.78,91.657 102.5,90.937 102.5,88.47 102.56,88.53 104.37,88.53 ; C61.1@104.324,95.29 C61.1@104.37,95.245 ; 105.554,100.32 105.58,100.32 ; C1.1@105.58,102.383 105.553,102.41 102.94,102.41 102.17,101.64 93.28,101.64 92.73,102.19 92.73,103.096 ; L1.1@107.224,102.383 L1.1@107.295,102.312 ; C72.1@109.45,150.092 C72.1@109.468,150.11 ; 92.635,132.485 93.26,133.11 ; 92.635,132.485 92.73,132.39 ; 92.635,132.485 92.73,132.39 ; 92.635,132.485 93.26,133.11 ; 92.73,103.096 RP1.8@94.66,103.096 92.73,103.096 ; 92.73,103.096 92.73,103.896 ; 92.73,103.896 RP1.7@94.66,103.896 92.73,103.896 ; 92.73,103.896 92.73,104.696 ; 92.73,104.696 92.73,105.496 ; 92.73,104.696 RP1.6@94.66,104.696 92.73,104.696 ; 92.73,105.496 RP1.5@94.66,105.496 92.73,105.496 ; 92.73,105.496 92.73,108.415 ; 92.73,108.415 RP2.8@94.631,108.415 92.73,108.415 ; 92.73,108.415 92.73,109.215 ; 92.73,109.215 RP2.7@94.631,109.215 92.73,109.215 ; 92.73,109.215 92.73,110.015 ; 92.73,110.015 RP2.6@94.631,110.015 92.73,110.015 ; 92.73,110.015 92.73,110.815 ; 92.73,110.815 RP2.5@94.631,110.815 92.73,110.815 ; 92.73,110.815 92.73,113.595 ; 92.73,113.595 94.28,113.595 92.73,113.595 ; 92.73,113.595 92.73,114.395 ; 92.73,114.395 94.28,114.395 92.73,114.395 ; 92.73,114.395 92.73,115.195 ; 92.73,115.195 94.28,115.195 92.73,115.195 ; 92.73,115.195 92.73,115.995 ; 92.73,115.995 RP3.5@94.28,115.995 ; 92.73,115.995 RP3.5@94.28,115.995 ; 92.73,115.995 92.73,118.83 ; 92.73,115.995 92.73,118.83 ; 92.73,115.995 RP3.5@94.28,115.995 ; 92.73,118.83 RP4.8@94.61,118.83 92.73,118.83 ; 92.73,118.83 92.73,119.63 ; 92.73,118.83 92.73,119.63 ; 92.73,119.63 92.73,120.43 ; 92.73,119.63 RP4.7@94.61,119.63 92.73,119.63 ; 92.73,119.63 92.73,120.43 ; 92.73,120.43 92.73,121.23 ; 92.73,120.43 RP4.6@94.61,120.43 92.73,120.43 ; 92.73,120.43 92.73,121.23 ; 92.73,121.23 92.73,124.04 ; 92.73,121.23 RP4.5@94.61,121.23 92.73,121.23 ; 92.73,121.23 92.73,124.04 ; 92.73,124.04 92.73,124.84 ; 92.73,124.04 RP5.8@94.6,124.04 92.73,124.04 ; 92.73,124.04 92.73,124.84 ; 92.73,124.84 92.73,125.64 ; 92.73,124.84 RP5.7@94.6,124.84 92.73,124.84 ; 92.73,124.84 92.73,125.64 ; 92.73,125.64 92.73,126.44 ; 92.73,125.64 RP5.6@94.6,125.64 92.73,125.64 ; 92.73,125.64 92.73,126.44 ; 92.73,126.44 92.73,129.22 ; 92.73,126.44 RP5.5@94.6,126.44 92.73,126.44 ; 92.73,126.44 92.73,129.22 ; 92.73,129.22 92.73,130.02 ; 92.73,129.22 RP6.8@94.6,129.22 92.73,129.22 ; 92.73,129.22 92.73,130.02 ; 92.73,130.02 92.73,130.82 ; 92.73,130.02 RP6.7@94.6,130.02 92.73,130.02 ; 92.73,130.02 92.73,130.82 ; 92.73,130.82 92.73,131.62 ; 92.73,130.82 RP6.6@94.6,130.82 92.73,130.82 ; 92.73,130.82 92.73,131.62 ; 92.73,131.62 92.73,132.39 ; 92.73,131.62 RP6.5@94.6,131.62 92.73,131.62 ; 92.73,131.62 92.73,132.39 ; 93.26,133.11 99.09,133.11 ; 93.26,133.11 99.09,133.11 ; 99.09,133.11 99.68,133.7 ; 99.09,133.11 99.68,133.7 ; R61.2@99.62,141.93 99.62,140.47 R62.2@99.63,140.47 99.63,139.07 R63.2@99.64,139.07 99.64,137.76 R64.2@99.65,137.76 99.65,136.45 R65.2@99.68,136.45 R66.2@99.68,135.14 ; R61.2@99.62,141.93 101.39,141.93 ; R61.2@99.62,141.93 101.39,141.93 ; 99.68,133.7 R66.2@99.68,135.14 ; 99.68,133.7 R66.2@99.68,135.14 ; 101.39,141.93 102.12,142.66 ; 101.39,141.93 102.12,142.66 ; 102.12,142.66 102.12,145.31 ; 102.12,142.66 102.12,145.31 ; 102.12,145.31 v4@105.75,148.94 ; 102.12,145.31 v4@105.75,148.94 ; v4@105.75,148.94 v4(105.77,148.94) v4@105.75,148.94
  Top Layer w0.8: J2.3@79.22,89.74 79.23,89.74 79.23,94.82 J2.1@79.22,94.82 ; 104.324,99.09 105.554,100.32 ; 105.58,100.32 C1.1@105.58,102.383 ; L3.1@107.295,98.68 L1.1@107.295,102.312
  Top Layer w1: C1.1@105.58,102.383 L1.1@107.224,102.383
  Top Layer w1.2: J2.1@79.22,94.82 94.08,94.82 98.35,99.09 104.324,99.09 ; 104.37,88.53 C61.1@104.37,95.245 ; 104.324,99.09 C61.1@104.324,95.29 104.324,99.09
  Bottom Layer w0.25: v5@112.13,166.5 v5(112.14,166.5) v5@112.13,166.5
  Bottom Layer w0.4: v1(146.3,158.24) 146.3,158.22 149.09,155.43 v3(149.09,155.29) ; 116.63,170.99 123.87,170.99 ; 116.63,170.99 v5(112.14,166.5) 116.63,170.99 ; 116.63,170.99 123.87,170.99 ; 123.87,170.99 126.15,168.71 ; 123.87,170.99 126.15,168.71 ; 126.15,168.71 132.43,168.71 ; 126.15,168.71 132.43,168.71 ; 132.43,168.71 133.7,167.44 ; 132.43,168.71 133.7,167.44 ; 133.7,164.97 v3(137,161.67) 133.7,164.97 ; 133.7,164.97 133.7,167.44 ; 133.7,164.97 133.7,167.44 ; v3(112.13,158.61) 112.13,166.5 v3(112.13,158.61)
  Bottom Layer w0.5: 105.78,152.09 105.78,156.47 ; 105.78,152.09 v4(105.77,148.94) 105.78,152.09 ; 105.78,152.09 105.78,156.47 ; 105.78,156.47 107.9,158.59 ; 105.78,156.47 107.9,158.59 ; 107.9,158.59 v3@112.11,158.59 ; 107.9,158.59 v3@112.11,158.59 ; v3@112.11,158.59 v3(112.13,158.61) v3@112.11,158.59
  other v3: 112.13,158.61 112.13,158.61 137,161.67
  other v5: 112.14,166.5 112.14,166.5
VSYNC: J5.10 J6.33 R18.1 | length 95.8
  Top Layer w0.25: v1(110.48,165.55) 110.48,162.714 114.67,158.524 J5.10@114.67,155.43 114.67,152.708 114.19,152.228 v1(114.19,151.51) ; J6.33@131.72,172.24 131.72,169.89 v2(131.91,169.89)
  Top Layer w0.3: v1(142.29,144.63) 142.29,137.18 144.56,134.91 R18.1@144.56,130.1
  Bottom Layer w0.25: v1(110.48,165.55) 110.48,167.236 117.214,173.97 130.516,173.97 131.86,172.626 131.86,169.89 v2(131.91,169.89)
  Bottom Layer w0.3: v1(114.19,151.51) 114.201,152.16 115.141,153.1 126.52,153.1 130.14,149.48 137.44,149.48 v1(142.29,144.63)
"": 
pads on no net: BL.3 BL.4 DC.3 J5.45 J5.49 J5.50 J6.37 J6.38 J6.39 J6.40 RP6.4 S1.3 S1.4 TP1.1 TP2.1 TP3.1 TP4.1 U1.44 U1.45 U1.46 U1.47 U1.48 U1.49 U1.50 U1.51 U1.52 U1.53 U1.54 U1.55 U1.56 U1.57 U1.58 U1.59 U1.60 U1.61 U1.65 U1.66 U1.67 U1.68 U1.69 U1.70 U1.71 U1.72 U1.73 U1.74 U1.77 U1.78 U1.79 U1.80 U1.81 U1.82 U1.83 U1.84 U1.85 U1.86 U1.87 U8.7 U9.4
copper on no net: | length 17.5
  Top Layer w0.1: 89.51,127.89 92.86,127.89 92.86,133.3 89.51,133.3 89.51,127.89

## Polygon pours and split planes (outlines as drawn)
GND on Top Layer (solid, remove dead copper): 178.22,76.2 178.22,178.21 92.99,178.21 92.42,177.64 92.42,144.35 93.33,143.44 142.06,143.44 143.44,142.06 143.44,133.41 147.92,128.93 147.92,123.27 152.86,118.33 152.86,84.8 165.45,84.8 165.45,76.2
GND on Bottom Layer (solid, remove dead copper, pour order 1): 178.21,76.35 178.21,178.16 92.99,178.16 92.4,177.57 92.4,144.32 93.09,143.63 141.67,143.63 143.34,141.96 143.34,133.31 147.75,128.9 147.75,123.34 152.84,118.25 152.84,84.88 165.49,84.88 165.49,76.35
GND on Top Layer (solid, remove dead copper, pour order 2): 165.68,76.29 76.2,76.29 76.2,178.24 91.45,178.24 91.95,177.74 91.95,144.24 93.37,142.82 140.6,142.82 142.69,140.73 142.69,132.94 146.87,128.76 146.87,122.68 152.25,117.3 152.25,84.82 152.93,84.14 159.7,84.14 159.7,83.12 160.55,82.27 165.68,82.27
GND on Bottom Layer (solid, remove dead copper, pour order 3): 165.55,76.26 77.05,76.26 77.05,178.16 91.02,178.16 91.8,177.38 91.8,143.79 92.88,142.71 140.88,142.71 142.73,140.86 142.73,133.06 146.96,128.83 146.96,122.71 152.09,117.58 152.09,84.91 152.73,84.27 159.96,84.27 159.96,82.9 160.47,82.39 165.55,82.39

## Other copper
Top Layer:
  region net $$$12717: 157.64,90.51 157.64,88.11 160.81,84.94 160.81,83.28 161.21,82.88 161.95,82.88 162.36,83.29 162.36,87.14 160.73,88.77 160.73,90.51
  region net $$$13350: 162.81,83.29 162.81,92.78 163.65,93.62 164.44,93.62 165.17,92.89 165.17,83.43 164.66,82.92 163.18,82.92
  region net $$$12717: 160.99,83.62 162.07,83.62 162.07,79.01 160.99,79.01
  region net $$$13350: 163,83.77 164.05,83.77 164.05,79 163,79
  region net +5V: 157.56,93.74 157.56,101.75 156.39,102.92 161.98,102.92 161.11,102.05 161.11,93.74

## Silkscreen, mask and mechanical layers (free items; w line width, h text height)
Top Overlay:
  lines w0.1: 91.23,133.32 91.23,134.1
  lines w0.2: 81.07,172.9 85.97,172.9 85.97,164.14 81.24,164.14 ; 85.11,169.77 85.95,169.77 ; 85.18,167.23 85.96,167.23
  text "GND" at 102.25,173.91 h1 r270
  text "GND" at 99.72,173.85 h1 r270
  text "GND" at 94.7,173.74 h1 r270
  text "GND" at 97.12,173.74 h1 r270
  text "DB4_SCS#" at 81.28,172.1 h0.8
  text "DB5_SDO" at 81.33,169.54 h0.8
  text "4 Line SPI" at 86.82,167.9 h1.5
  text "DB6_SDI" at 81.37,166.98 h0.8
  text "DB7_SCLK" at 81.25,164.46 h0.8
  text "SDA" at 150.38,162.7 h1
  text "SCL" at 153.04,162.7 h1
  text "DB0" at 81,157.89 h0.8
  text "DB1" at 81.02,155.42 h0.8
  text "DB2" at 81.06,152.74 h0.8
  text "8080" at 85.64,152.31 h1.5
  text "6800" at 85.6,150.54 h1.5
  text "DB3" at 80.98,150.34 h0.8
  text "Vcom" at 102.87,148.58 h1
  text "DB4_SCS#" at 80.94,147.85 h0.8
  text "AVDD" at 147.2,146.94 h1
  text "DB5_SDO" at 80.99,145.29 h0.8
  text "TEST2" at 90.17,142.82 h0.8
  text "DB6_SDI" at 81.03,142.73 h0.8
  text "DB7_SCLK" at 80.91,140.21 h0.8
  text "DB8" at 81.03,137.63 h0.8
  text "DB9" at 81.03,135.09 h0.8
  text "VGL" at 154.45,133.54 h1
  text "DB10" at 81.07,132.53 h0.8
  text "TEST2" at 90.11,132.37 h0.8
  text "TEST1" at 90.12,131.54 h0.8
  text "TEST0" at 90.09,130.69 h0.8
  text "DB11" at 81.08,129.99 h0.8
  text "PS0" at 90.16,129.77 h0.8
  text "PS1" at 90.16,128.99 h0.8
  text "PS2" at 90.17,128.2 h0.8
  text "DB12" at 81.07,127.44 h0.8
  text "DB13" at 81.07,124.94 h0.8
  text "DB14" at 81.22,122.38 h0.8
  text "DB15" at 81.26,119.83 h0.8
  text "VGH" at 155.26,118.76 h1
  text "CS#" at 81.28,117.33 h0.8
  text "RD#" at 81.19,114.73 h0.8
  text "WR#" at 81.21,112.26 h0.8
  text "RS/A0" at 81.24,109.68 h0.8
  text "LT768-RST" at 81.22,107.19 h0.8
  text "WAIT" at 81.26,104.65 h0.8
  text "INT" at 81.24,102.09 h1
  text "LEVETOP" at 134.76,100.06 h5
  text "GND" at 81.24,99.62 h1
  text "LT768  V1.0" at 140.74,97.21 h2
  text "MCU" at 78.09,96.95 h1
  text "3.3V" at 81.06,94.43 h1
  text "3.3V" at 81,91.94 h1
  text "3.3V" at 81.06,89.38 h1
  text "GND" at 81.06,86.86 h1
  text "CS0" at 110.73,84.6 h1.5
  text "CS1" at 113.45,84.62 h1.5
  text "SO" at 116.19,84.6 h1.5
  text "SI" at 118.87,84.58 h1.5
  text "SCLK" at 120.69,84.55 h1.5
  text "3.3V" at 123.75,84.51 h1.5
  text "GND" at 126.55,84.48 h1.5
  text "GND" at 81.04,84.37 h1
  text "DC+5V" at 166.65,84.2 h2.5
  text "GND" at 81.1,81.77 h1
  text "+" at 139.16,80.27 h1.5
  text "-" at 141.63,80.27 h1.5
  text "BL" at 81.2,79.09 h1
  text "+5V" at 95.57,76.74 h1.5
  text "GND" at 92.97,76.68 h1.5
Bottom Overlay:
  text "LEVETOP" at 135.66,173.2 h4
  text "http://www.levetop.cn/" at 141.86,170.19 h3
Mechanical 1:
  lines w0.254: 76.72,76.24 178.22,76.24 178.22,178.24 76.72,178.24 76.72,76.24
